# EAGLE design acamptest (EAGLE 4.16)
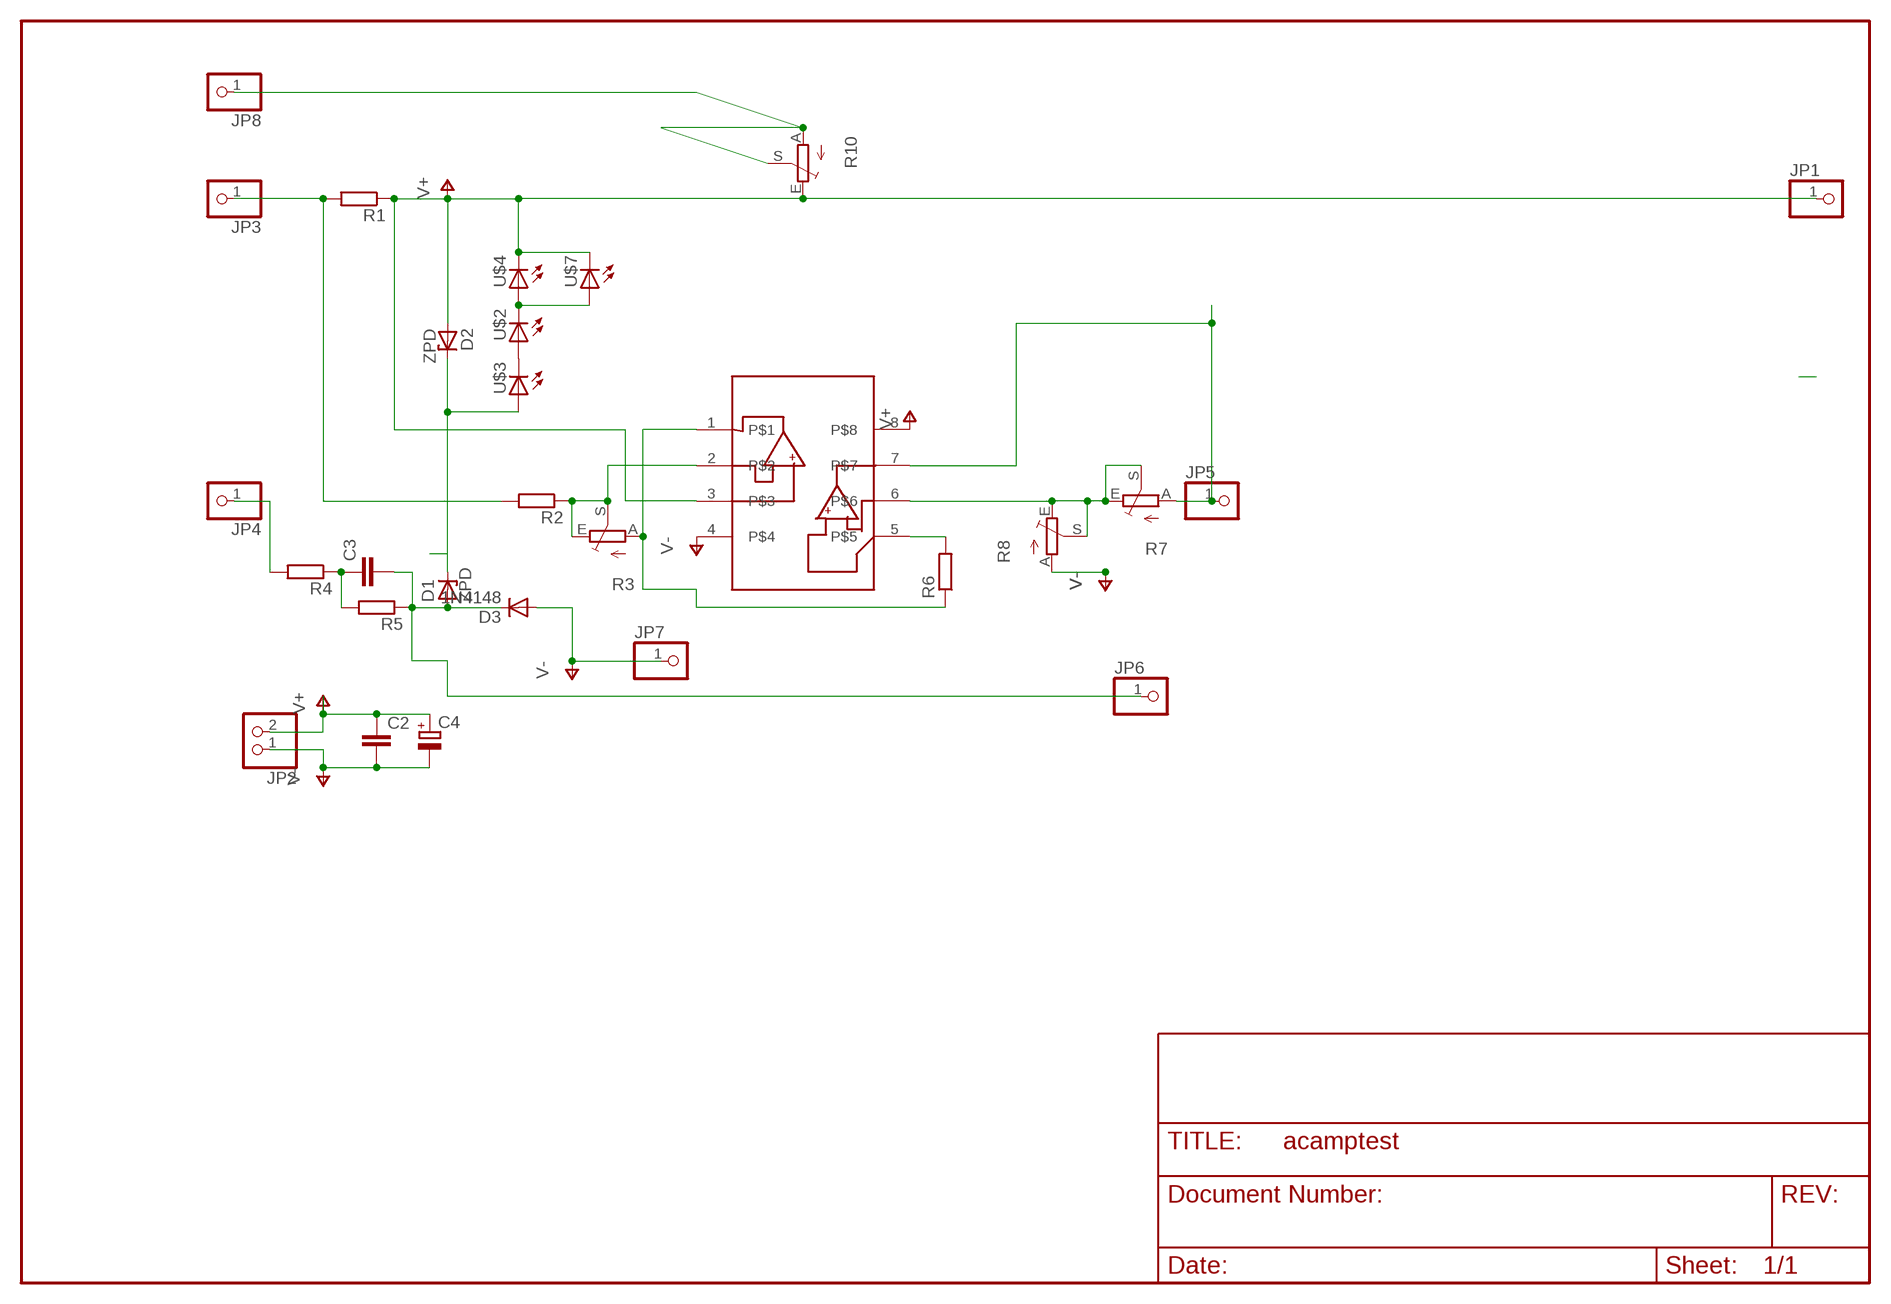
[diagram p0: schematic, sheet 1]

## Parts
C2  C-EU050-024X044  [C050-024X044]
C3  C-EU075-042X103  [C075-042X103]
C4  CPOL-EUE2-5  [E2-5]
D1  ZPD  [DO35Z10]
D2  ZPD  [DO35Z10]
D3  1N4148  [DO35-10]
JP1  PINHD-1X1  [1X01]
JP2  PINHD-1X2  [1X02]
JP3  PINHD-1X1  [1X01]
JP4  PINHD-1X1  [1X01]
JP5  PINHD-1X1  [1X01]
JP6  PINHD-1X1  [1X01]
JP7  PINHD-1X1  [1X01]
JP8  PINHD-1X1  [1X01]
R1  R-EU_0207/15  [0207/15]
R2  R-EU_0207/15  [0207/15]
R3  TRIM_EU-LI15  [LI15]
R4  R-EU_0207/15  [0207/15]
R5  R-EU_0207/15  [0207/15]
R6  R-EU_0207/15  [0207/15]
R7  TRIM_EU-LI15  [LI15]
R8  TRIM_EU-LI15  [LI15]
R10  TRIM_EU-LI15  [LI15]
U$1  MCP6042SOIC  [SO-08]
U$2  LEDCHIPLED_0805  [CHIPLED_0805]
U$3  LEDCHIPLED_0805  [CHIPLED_0805]
U$4  LEDCHIPLED_0805  [CHIPLED_0805]
U$7  LEDP-LCC-4  [P-LCC-4]

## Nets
AC(N): JP3.1 R1.2 R2.2
N$1: JP5.1 R7.A U$1.7
N$2: R7.E R7.S R8.E R8.S U$1.6
N$3: R2.1 R3.E R3.S U$1.2
N$4: R3.A R6.1 U$1.1
N$5: R6.2 U$1.5
N$6: U$2.A U$3.C
N$7: U$2.C U$4.A U$7.A
N$8: D1.C D2.C U$3.A
N$9: JP8.1 R10.A R10.S
N$12: C3.1 R4.1 R5.2
N$13: JP4.1 R4.2
N$14: C3.2 D1.A D3.C JP6.1 R5.1
V+: C2.1 C4.+ D2.A JP1.1 JP2.2 R1.1 R10.E U$1.3 U$1.8 U$4.C U$7.C@4(C)
V-: C2.2 C4.- D3.A JP2.1 JP7.1 R8.A U$1.4

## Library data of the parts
C2 = rcl:C-EU: CAPACITOR, European symbol
C3 = rcl-2:C-EU: CAPACITOR, European symbol
C4 = rcl-2:CPOL-EU: POLARIZED CAPACITOR, European symbol
D1 D2 = diode:ZPD: Z DIODE
D3 = diode-1:1N4148: DIODE
JP1 JP3-JP8 = pinhead(2):PINHD-1X1: PIN HEADER
JP2 = pinhead:PINHD-1X2: PIN HEADER
R1 R2 R4-R6 = rcl:R-EU_: RESISTOR, European symbol
R3 R7 R8 R10 = pot:TRIM_EU-: POTENTIOMETER
U$1 = microchip-3:MCP6042
U$2-U$4 U$7 = led(3):LED: LED

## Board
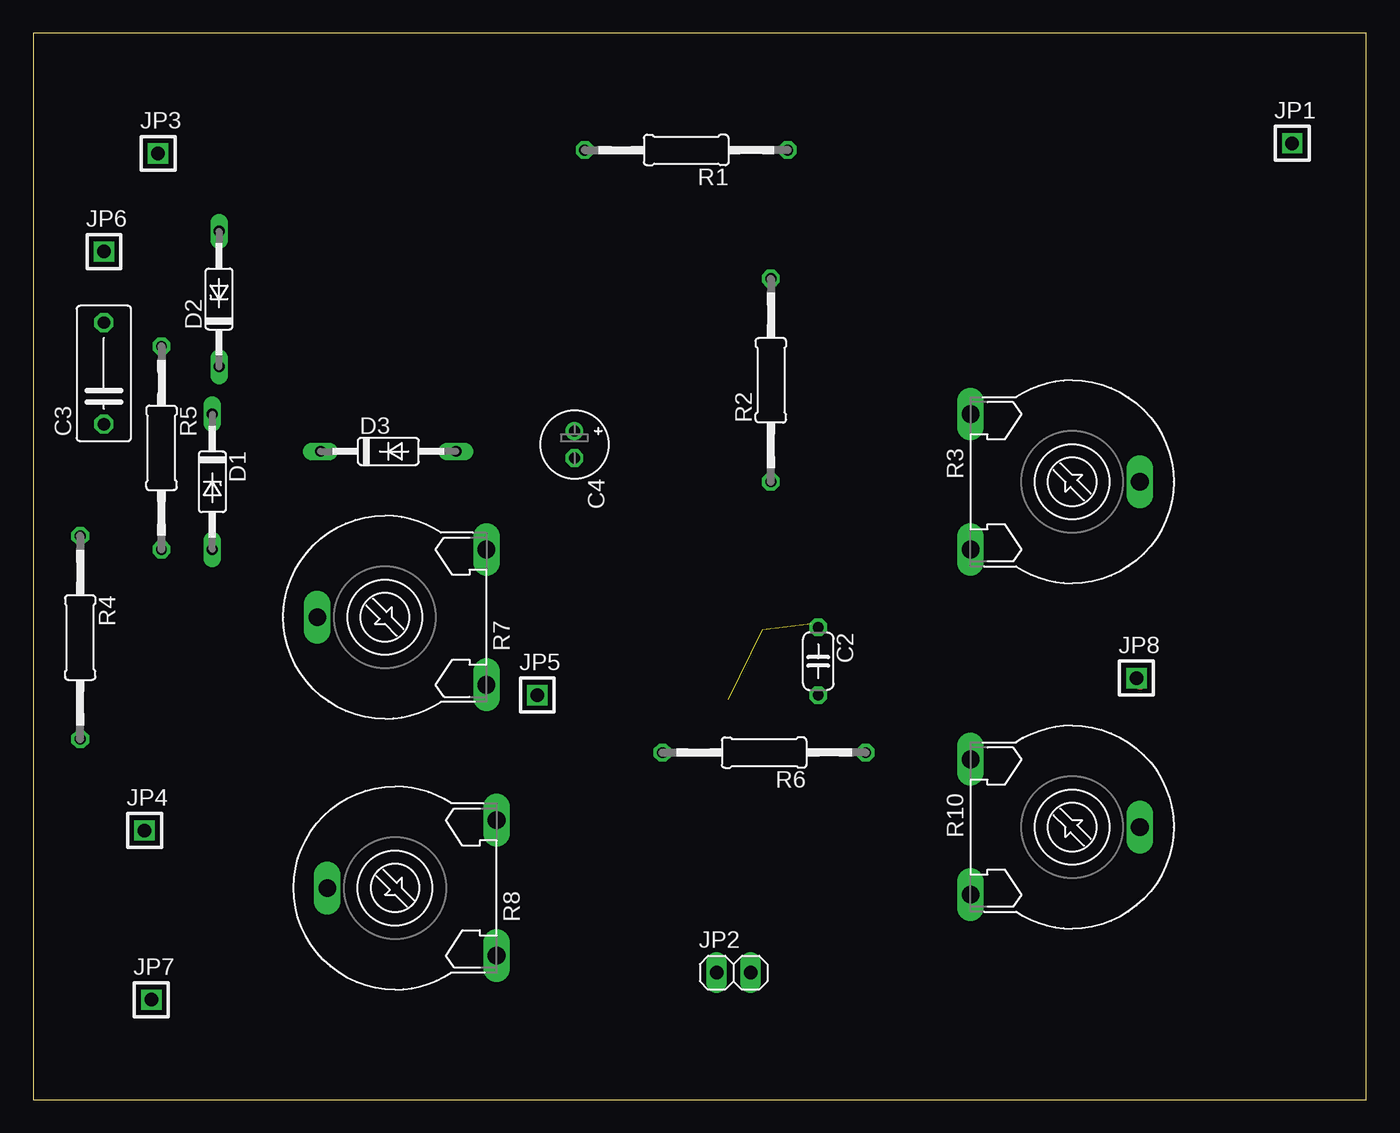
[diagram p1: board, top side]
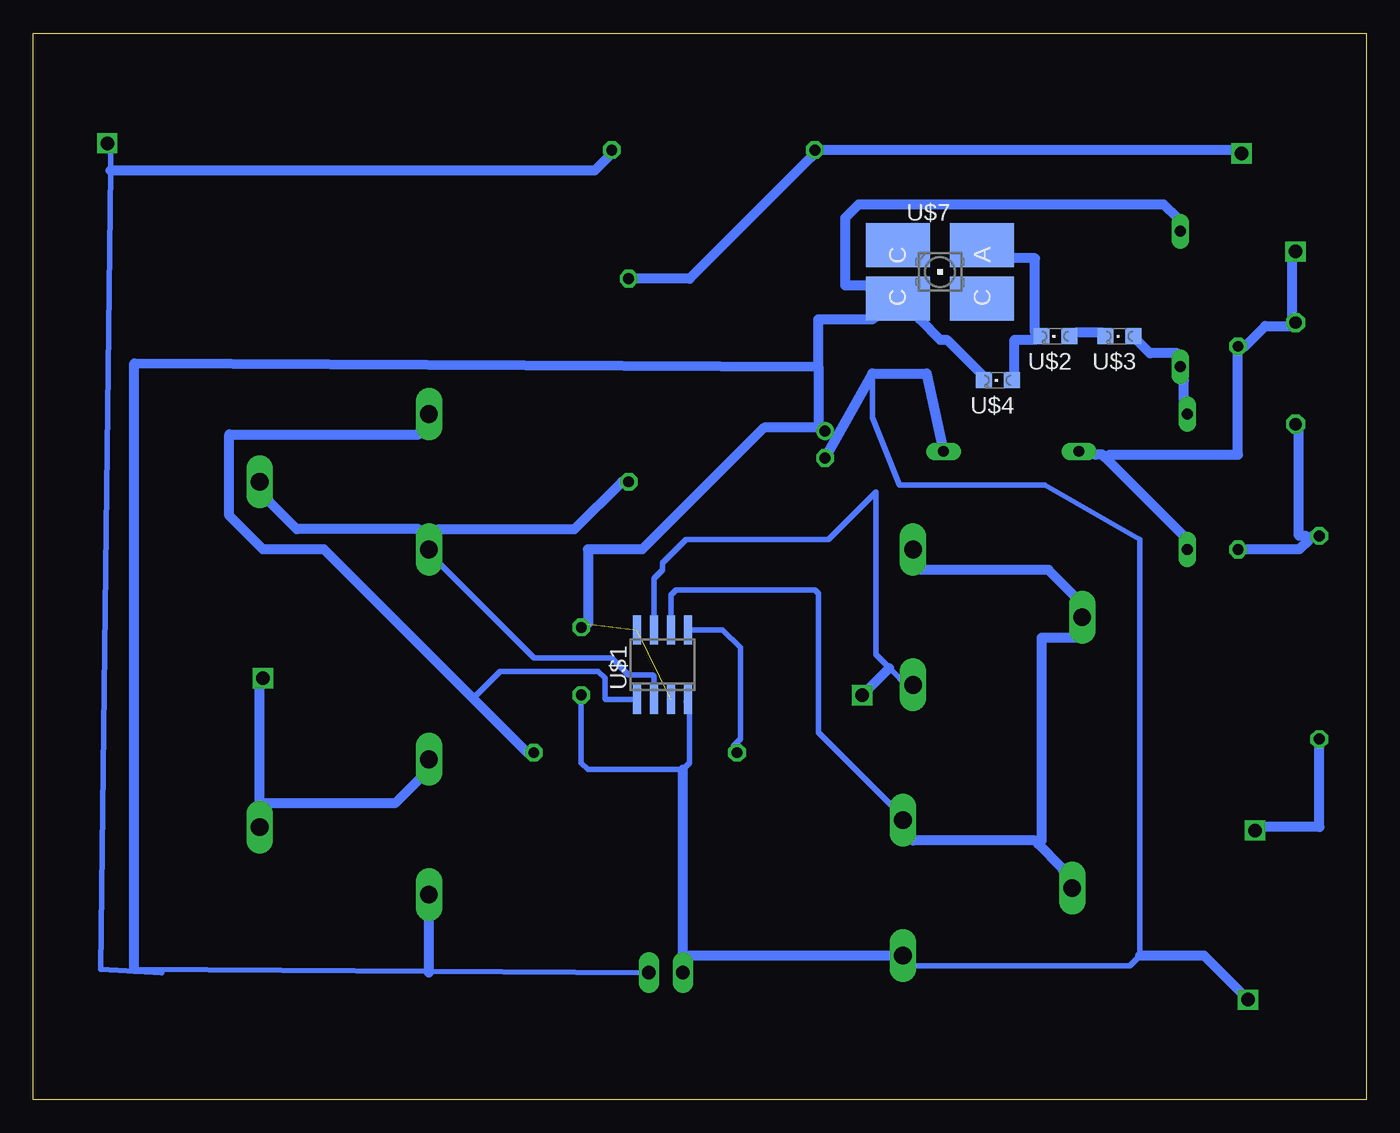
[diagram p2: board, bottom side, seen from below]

Size 100 x 80 mm. Coordinates in mm from the lower left corner, seen from the top.
Outline: 0,0 100,0 100,80 0,80 0,0
Copper layers (1*16): Top 0.035mm / dielectric 1.5mm / Bottom 0.035mm
Design rules "default": minimum track width 30mil, minimum drill 24mil, track to track 30mil, track to pad 30mil, pad to pad 8mil, via to via 8mil, smd to smd 8mil, copper to edge 40mil, drill to drill 20mil, minimum pad ring 10mil, minimum via ring 8mil, stop-mask expansion 4mil, vias tented up to drill 0mil, thermal gap 10mil

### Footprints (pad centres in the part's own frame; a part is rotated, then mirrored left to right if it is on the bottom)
C050-024X044 = drill 0.813 octagon: 1 -2.54,0; 2 2.54,0
C075-042X103 = drill 0.914 octagon: 1 -3.81,0; 2 3.81,0
E2-5 = drill 0.813 pad 1.27 round: + -1.016,0 | drill 0.813 pad 1.27 octagon: - 1.016,0
DO35Z10 = drill 0.813 long: A 5.08,0; C -5.08,0
DO35-10 = drill 0.813 long: A 5.08,0; C -5.08,0
1X01 = drill 1.016 square: 1 0,0
1X02 = drill 1.016 long: 1 -1.27,0; 2 1.27,0
0207/15 = drill 0.813 octagon: 1 -7.62,0; 2 7.62,0
LI15 = drill 1.321 long: A -5.08,-7.62; E 5.08,-7.62; S 0,5.08
SO-08 = smd 0.6 x 2.2: 1 -1.905,-2.6; 2 -0.635,-2.6; 3 0.635,-2.6; 4 1.905,-2.6; 5 1.905,2.6; 6 0.635,2.6; 7 -0.635,2.6; 8 -1.905,2.6
CHIPLED_0805 = smd 1.2 x 1.2: A 0,-1.05; C 0,1.05
P-LCC-4 = smd 3.3 x 4.8: A -2,3.15; C@1 -2,-3.15; C@3 2,3.15; C@4 2,-3.15

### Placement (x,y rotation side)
C2  58.89,32.89 270 top
C3  5.3,54.48 90 top
C4  40.6,49.14 270 top
D1  13.42,46.35 270 top
D2  13.93,60.07 90 top
D3  26.63,48.64 0 top
JP1  94.45,71.75 0 top
JP2  52.54,9.52 0 top
JP3  9.36,70.99 0 top
JP4  8.34,20.19 0 top
JP5  37.81,30.35 0 top
JP6  5.3,63.62 0 top
JP7  8.85,7.49 0 top
JP8  82.77,31.62 0 top
R1  48.98,71.24 180 top
R2  55.33,53.97 90 top
R3  77.94,46.35 270 top
R4  3.52,34.67 270 top
R5  9.61,48.89 270 top
R6  54.83,26.03 180 top
R7  26.38,36.19 90 top
R8  27.14,15.87 90 top
R10  77.94,20.44 270 top
U$1  52.79,32.63 0 bottom
U$2  23.33,57.27 90 bottom
U$3  18.5,57.27 90 bottom
U$4  27.65,53.97 90 bottom
U$7  31.97,62.1 270 bottom

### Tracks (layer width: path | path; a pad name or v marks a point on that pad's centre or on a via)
AC(N)
  Bottom 0.762: R2.2 50.76,61.59 41.62,70.73 R1.2 9.61,71.24 JP3.1
N$1
  Bottom 0.406: U$1.7 53.43,39.11 52.79,39.75 52.79,40.25 51.02,42.03 40.35,42.03 36.79,45.59 36.79,33.4 35.78,32.38 34.25,30.86 R7.A
  Bottom 0.762: 35.78,32.38 JP5.1
N$2
  Bottom 0.406: U$1.6 52.16,37.84 51.78,38.22 41.36,38.22 41.11,37.97 41.11,27.55 34.51,20.95 R8.E
  Bottom 0.762: 24.6,19.17 24.85,19.43 34,19.43 R8.E | 24.6,19.17 22.82,17.39 R8.S | R7.E 33.49,39.75 23.84,39.75 21.81,37.71 R7.S 21.81,34.67 24.35,34.67 24.35,19.43 24.6,19.17
N$3
  Bottom 0.406: U$1.2 53.43,31.74 53.56,31.87 55.33,31.87 56.6,33.14 62.45,33.14 70.57,41.27 R3.E
  Bottom 0.762: R2.1 55.84,46.35 59.4,42.79 69.56,42.79 R3.E 71.08,42.79 80.23,42.79 82.26,44.83 R3.S
N$4
  Bottom 0.406: U$1.1 57.05,30.03 57.11,30.09 57.11,31.62 57.62,32.13 64.99,32.13 67.02,30.09
  Bottom 0.762: R6.1 62.95,26.03 67.02,30.09 78.19,41.27 82.77,41.27 85.31,43.81 85.31,49.91 71.08,49.91 R3.A
N$5
  Bottom 0.406: U$1.5 48.28,35.23 46.95,33.9 46.95,27.05 47.46,26.54 47.46,26.03 47.21,25.78 R6.2
N$6
  Bottom 0.762: U$3.C 19.77,57.53 21.81,57.53 U$2.A
N$7
  Bottom 0.762: U$4.A 26.38,54.48 26.38,57.02 24.85,57.02 U$2.C 24.85,57.53 24.85,63.11 26.89,63.11 U$7.A
N$8
  Bottom 0.762: U$3.A 17.23,57.02 16.22,56 14.19,56 D2.C 13.68,53.97 13.68,52.45 D1.C
N$9
  Top 0.762: JP8.1 83.02,31.11
  Bottom 0.762: 83.02,22.22 72.86,22.22 70.32,24.76 R10.A | 83.02,22.22 83.02,31.11 JP8.1 | 83.02,22.22 R10.S
N$12
  Bottom 0.762: 4.28,42.03 5.04,41.27 R5.2 | 4.28,42.03 4.03,42.29 R4.1 | C3.1 5.04,50.41 5.04,42.29 4.53,42.29 4.28,42.03
N$13
  Bottom 0.762: R4.2 3.52,20.44 8.09,20.44 JP4.1
N$14
  Bottom 0.762: JP6.1 5.55,63.11 5.55,58.54 C3.2 5.55,58.03 7.58,58.03 9.11,56.51 R5.1 9.61,48.38 19.27,48.38 19.52,48.13 | 19.52,48.13 19.77,48.38 20.28,48.38 D3.C | 19.52,48.13 13.68,42.29 D1.A
V+  (2 unrouted)
  Bottom 0.406: JP2.2 70.32,9.63 92.42,9.77 90.39,9.52 94.96,9.77 94.2,69.72 94.2,71.24 94.7,71.75
  Bottom 0.762: R1.1 56.86,70.73 57.87,69.72 94.2,69.72 | U$4.C 28.92,54.48 31.46,57.02 31.97,57.02 33.49,58.54 U$7.C@4 | D2.A 14.19,66.16 15.2,67.18 38.06,67.18 39.08,66.16 39.08,61.08 37.05,61.08 U$7.C@4 | 41.11,54.99 41.11,58.54 37.05,58.54 U$7.C@4 | 41.11,54.99 41.11,50.41 | 41.11,50.41 45.17,50.41 54.32,41.27 58.38,41.27 58.38,35.68 C2.1 | 41.11,50.41 C4.+ | 41.11,54.99 92.42,55.24 92.42,9.77 | 94.2,71.24 JP1.1 | R10.E 70.32,9.52 70.32,9.63
V-
  Bottom 0.406: C2.2 58.89,25.27 58.38,24.76 51.27,24.76 50.76,25.27 50.76,29.59 51.02,29.84 50.89,29.97 U$1.4 | 37.05,54.48 37.05,51.18 35.01,46.1 24.09,46.1 16.98,42.03 16.98,10.79 17.74,10.03 34.51,10.03 35.01,10.54 R8.A
  Bottom 0.762: D3.A 32.98,54.48 37.05,54.48 C4.- | 51.27,24.76 JP2.1 50.76,10.79 R8.A | JP7.1 12.15,10.79 16.98,10.79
